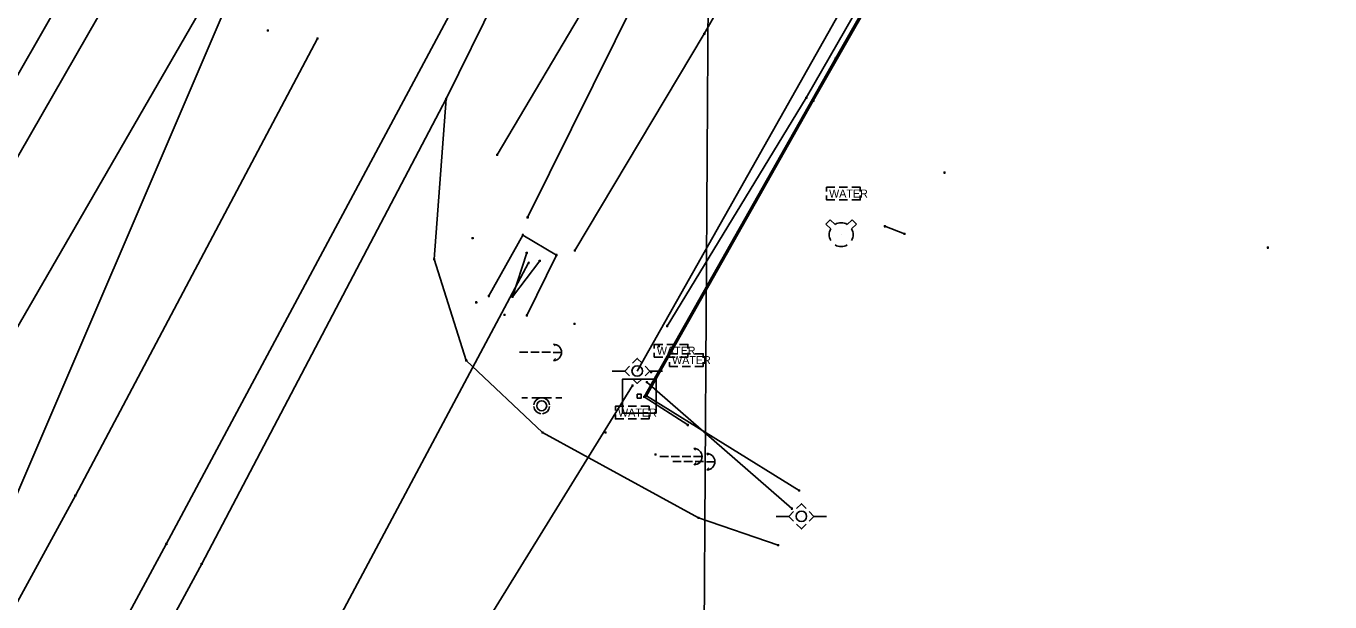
# Model space of a CAD drawing. Extents: x 1954856 to 2011933, y 399149 to 426294.
# Drawn here: x 2006462.2 to 2006616.9, y 401965.3 to 402033.7 of the extents above; entities that cross this region are included whole.
import ezdxf

# ---------------------------------------------------------------- set-up
doc = ezdxf.new("R2010")
doc.units = 0
for name, color, linetype in [('BankMent_ep', 7, 'Continuous'), ('BaselineSurvey', 7, 'Continuous'), ('Driveway_ep', 7, 'Continuous'), ('ElecAer_ep', 7, 'Continuous'), ('EndTreatMES_ep', 7, 'Continuous'), ('Fence_ep', 7, 'Continuous'), ('FireHydrant_ep', 7, 'Continuous'), ('FlowLineInvert_ep', 7, 'Continuous'), ('GovTwpRgeLine_ep', 7, 'Continuous'), ('GuyWireAnchor_ep', 7, 'Continuous'), ('MeterWater_ep', 7, 'Continuous'), ('MonumentCC_ep', 7, 'Continuous'), ('PavtAsphalt_ep', 7, 'Continuous'), ('PipeCulvert_ep', 7, 'Continuous'), ('PMRK_ep', 7, 'Continuous'), ('PointLocator_ep', 7, 'Continuous'), ('PoleShared_ep', 7, 'Continuous'), ('ShldrPaved_ep', 7, 'Continuous'), ('SignSingle_ep', 7, 'Continuous'), ('WaterB_ep', 7, 'Continuous')]:
    doc.layers.add(name, color=color, linetype=linetype)

msp = doc.modelspace()

# ---------------------------------------------------------------- linework, layer by layer
at = {"layer": 'BankMent_ep'}
msp.add_line((2006518.06, 402018.39), (2006530.32, 402039.07), dxfattribs=at)
for points in [[(2006521.67, 402010.95), (2006534.68, 402037.21), (2006577.7, 402108.71), (2006586.6, 402125.35), (2006592.77, 402136.09)], [(2006527.27, 402007.04), (2006542.64, 402032.74), (2006583.85, 402104.85), (2006594.17, 402121.51), (2006599.57, 402131.14)], [(2006538.23, 401998.06), (2006554.74, 402025.13), (2006596.91, 402098.52), (2006605.55, 402113.85), (2006610.04, 402126.13)]]:
    msp.add_lwpolyline(points, dxfattribs=at)
at = {"layer": 'BaselineSurvey'}
msp.add_lwpolyline([(2006095.1, 401364.22), (2006751.44, 402500.64), (2007687.69, 404121.69)], dxfattribs=at)
at = {"layer": 'Driveway_ep'}
msp.add_lwpolyline([(2006512.02, 402025.04), (2006510.58, 402006), (2006514.39, 401993.98), (2006523.44, 401985.42), (2006541.96, 401975.28), (2006551.4, 401972.05)], dxfattribs=at)
at = {"layer": 'ElecAer_ep'}
for points in [[(2006534.68, 401992.72), (2006720.73, 402322.24), (2006754.67, 402382.35)], [(2006462.32, 401874.62), (2006534.11, 401990.99)], [(2006535.81, 401991.41), (2006553.03, 401976.39)]]:
    msp.add_lwpolyline(points, dxfattribs=at)
at = {"layer": 'EndTreatMES_ep'}
for p, q in [((2006517.08, 402001.63), (2006521.12, 402008.86)), ((2006521.12, 402008.86), (2006525.08, 402006.48)), ((2006525.08, 402006.48), (2006521.57, 401999.32))]:
    msp.add_line(p, q, dxfattribs=at)
msp.add_lwpolyline([(2006523.1, 402005.79), (2006519.86, 402001.54), (2006521.56, 402006.75)], dxfattribs=at)
at = {"layer": 'Fence_ep'}
for points in [[(2006540.67, 401986.32), (2006535.51, 401989.65), (2006558.22, 402029.79), (2006609.19, 402119), (2006624.81, 402146.2)], [(2006553.9, 401978.53), (2006535.79, 401989.79), (2006555.57, 402024.8), (2006597.81, 402098.72), (2006606.19, 402113.32)]]:
    msp.add_lwpolyline(points, dxfattribs=at)
at = {"layer": 'FireHydrant_ep'}
for p, q in [((2006557.05, 402010.14), (2006557.58, 402010.68)), ((2006557.58, 402010.68), (2006558.16, 402010.12)), ((2006560.18, 402010.68), (2006559.6, 402010.12)), ((2006560.7, 402010.14), (2006560.18, 402010.68)), ((2006557.05, 402010.14), (2006557.64, 402009.58)), ((2006558.88, 402008.9), (2006558.88, 402008.9)), ((2006560.7, 402010.14), (2006560.12, 402009.58))]:
    msp.add_line(p, q, dxfattribs=at)
for start, end in [(59.4735, 120.5265), (151.2674, 208.7326), (331.2674, 28.7326), (239.4735, 300.5265)]:
    msp.add_arc((2006558.88, 402008.9), 1.42, start, end, dxfattribs=at)
at = {"layer": 'FlowLineInvert_ep'}
for p, q in [((2006521.88, 402005.47), (2006521.7, 402005.64)), ((2006521.88, 402005.64), (2006521.7, 402005.47)), ((2006521.79, 402005.55), (2006521.79, 402005.55))]:
    msp.add_line(p, q, dxfattribs=at)
at = {"layer": 'GovTwpRgeLine_ep'}
msp.add_line((2006528.85, 399746.53), (2006545.38, 402407.42), dxfattribs=at)
at = {"layer": 'GuyWireAnchor_ep'}
for p, q in [((2006520.7, 401994.94), (2006521.7, 401994.94)), ((2006522.04, 401994.94), (2006523.04, 401994.94)), ((2006523.37, 401994.94), (2006524.37, 401994.94)), ((2006524.7, 401994.93), (2006525.7, 401994.93)), ((2006524.73, 401995.9), (2006524.92, 401995.71)), ((2006525.7, 401994.93), (2006525.7, 401994.93)), ((2006524.74, 401993.95), (2006524.98, 401994.19)), ((2006537.37, 401982.57), (2006538.37, 401982.57)), ((2006538.7, 401982.57), (2006539.7, 401982.57)), ((2006540.03, 401982.57), (2006541.03, 401982.57)), ((2006541.37, 401982.56), (2006542.37, 401982.56)), ((2006541.39, 401983.53), (2006541.59, 401983.34)), ((2006542.37, 401982.56), (2006542.37, 401982.56)), ((2006542.92, 401982.93), (2006543.11, 401982.74)), ((2006538.89, 401981.97), (2006539.89, 401981.97)), ((2006540.22, 401981.97), (2006541.22, 401981.97)), ((2006541.41, 401981.58), (2006541.65, 401981.82)), ((2006541.56, 401981.97), (2006542.56, 401981.97)), ((2006542.89, 401981.96), (2006543.89, 401981.96)), ((2006542.93, 401980.98), (2006543.17, 401981.22)), ((2006543.89, 401981.96), (2006543.89, 401981.96))]:
    msp.add_line(p, q, dxfattribs=at)
for centre in [(2006524.73, 401994.93), (2006541.4, 401982.56), (2006542.92, 401981.96)]:
    msp.add_arc(centre, 0.973, 271.14, 90.0059, dxfattribs=at)
at = {"layer": 'MeterWater_ep'}
for p, q in [((2006559.14, 402013.78), (2006559.14, 402013.78)), ((2006538.7, 401995.13), (2006538.7, 401995.13)), ((2006540.51, 401994.02), (2006540.51, 401994.02)), ((2006534.09, 401987.79), (2006534.09, 401987.79))]:
    msp.add_line(p, q, dxfattribs=at)
for points in [[(2006557.14, 402014.03), (2006557.14, 402014.53), (2006558.14, 402014.53)], [(2006558.14, 402013.03), (2006557.14, 402013.03), (2006557.14, 402013.53)], [(2006558.64, 402014.53), (2006559.64, 402014.53)], [(2006560.14, 402014.53), (2006561.14, 402014.53), (2006561.14, 402014.03)], [(2006561.14, 402013.53), (2006561.14, 402013.03), (2006560.14, 402013.03)], [(2006559.64, 402013.03), (2006558.64, 402013.03)], [(2006536.7, 401995.38), (2006536.7, 401995.88), (2006537.7, 401995.88)], [(2006537.7, 401994.38), (2006536.7, 401994.38), (2006536.7, 401994.88)], [(2006538.2, 401995.88), (2006539.2, 401995.88)], [(2006539.7, 401995.88), (2006540.7, 401995.88), (2006540.7, 401995.38)], [(2006540.7, 401994.88), (2006540.7, 401994.38), (2006539.7, 401994.38)], [(2006539.2, 401994.38), (2006538.2, 401994.38)], [(2006538.51, 401994.27), (2006538.51, 401994.77), (2006539.51, 401994.77)], [(2006539.51, 401993.26), (2006538.51, 401993.26), (2006538.51, 401993.77)], [(2006540.01, 401994.77), (2006541.01, 401994.77)], [(2006541.01, 401993.26), (2006540.01, 401993.26)], [(2006541.51, 401994.77), (2006542.51, 401994.77), (2006542.51, 401994.27)], [(2006542.51, 401993.77), (2006542.51, 401993.26), (2006541.51, 401993.26)], [(2006532.09, 401988.04), (2006532.09, 401988.54), (2006533.09, 401988.54)], [(2006533.09, 401987.04), (2006532.09, 401987.04), (2006532.09, 401987.54)], [(2006533.59, 401988.54), (2006534.59, 401988.54)], [(2006535.09, 401988.54), (2006536.09, 401988.54), (2006536.09, 401988.04)], [(2006536.09, 401987.54), (2006536.09, 401987.04), (2006535.09, 401987.04)], [(2006534.59, 401987.04), (2006533.59, 401987.04)]]:
    msp.add_lwpolyline(points, dxfattribs=at)
at = {"layer": 'MonumentCC_ep'}
msp.add_line((2006534.92, 401989.74), (2006534.92, 401989.74), dxfattribs=at)
msp.add_lwpolyline([(2006532.92, 401987.73), (2006536.92, 401987.73), (2006536.92, 401991.74), (2006532.92, 401991.74), (2006532.92, 401987.73)], dxfattribs=at)
msp.add_lwpolyline([(2006534.68, 401989.5), (2006534.68, 401989.97), (2006535.16, 401989.97), (2006535.16, 401989.5)], close=True, dxfattribs=at)
at = {"layer": 'PavtAsphalt_ep'}
for p, q in [((2006486.83, 402062.9), (2006445.85, 401991.54)), ((2006478.79, 401972.18), (2006518.02, 402045.52))]:
    msp.add_line(p, q, dxfattribs=at)
msp.add_lwpolyline([(2006359.89, 401758.81), (2006367.15, 401771.41), (2006374.34, 401784.06), (2006381.49, 401796.73), (2006387.49, 401807.37), (2006393.48, 401818.01), (2006399.46, 401828.66), (2006409.74, 401847.01), (2006420.01, 401865.38), (2006430.26, 401883.75), (2006433.55, 401889.65), (2006436.84, 401895.56), (2006440.13, 401901.47), (2006453.14, 401924.97), (2006466.04, 401948.54), (2006478.79, 401972.18)], dxfattribs=at)
at = {"layer": 'PipeCulvert_ep'}
msp.add_lwpolyline([(2006521.79, 402005.55), (2006493.24, 401952.06)], dxfattribs=at)
at = {"layer": 'PMRK_ep'}
msp.add_line((2006454.18, 401962.09), (2006486.86, 402038.25), dxfattribs=at)
msp.add_lwpolyline([(2006391.58, 401838.69), (2006429.54, 401907.47), (2006468, 401977.95), (2006496.74, 402032.18)], dxfattribs=at)
at = {"layer": 'PointLocator_ep'}
for p, q in [((2006490.97, 402033.13), (2006490.72, 402033.13)), ((2006490.85, 402033.01), (2006490.85, 402033.26)), ((2006490.85, 402033.13), (2006490.85, 402033.13)), ((2006496.87, 402032.18), (2006496.62, 402032.18)), ((2006496.74, 402032.06), (2006496.74, 402032.31)), ((2006496.74, 402032.18), (2006496.74, 402032.18)), ((2006542.77, 402032.74), (2006542.52, 402032.74)), ((2006542.64, 402032.62), (2006542.64, 402032.87)), ((2006542.64, 402032.74), (2006542.64, 402032.74)), ((2006558.34, 402029.79), (2006558.09, 402029.79)), ((2006558.22, 402029.67), (2006558.22, 402029.92)), ((2006558.22, 402029.79), (2006558.22, 402029.79)), ((2006512.14, 402025.04), (2006511.89, 402025.04)), ((2006512.02, 402024.91), (2006512.02, 402025.16)), ((2006512.02, 402025.04), (2006512.02, 402025.04)), ((2006554.87, 402025.13), (2006554.62, 402025.13)), ((2006554.74, 402025.01), (2006554.74, 402025.26)), ((2006554.74, 402025.13), (2006554.74, 402025.13)), ((2006555.7, 402024.8), (2006555.45, 402024.8)), ((2006555.57, 402024.68), (2006555.57, 402024.93)), ((2006555.57, 402024.8), (2006555.57, 402024.8)), ((2006518.18, 402018.39), (2006517.93, 402018.39)), ((2006518.06, 402018.26), (2006518.06, 402018.51)), ((2006518.06, 402018.39), (2006518.06, 402018.39)), ((2006571.27, 402016.27), (2006571.02, 402016.27)), ((2006571.15, 402016.14), (2006571.15, 402016.39)), ((2006571.15, 402016.27), (2006571.15, 402016.27)), ((2006521.8, 402010.95), (2006521.55, 402010.95)), ((2006521.67, 402010.83), (2006521.67, 402011.08)), ((2006521.67, 402010.95), (2006521.67, 402010.95)), ((2006521.24, 402008.86), (2006520.99, 402008.86)), ((2006521.12, 402008.74), (2006521.12, 402008.99)), ((2006521.12, 402008.86), (2006521.12, 402008.86)), ((2006564.18, 402009.9), (2006563.93, 402009.9)), ((2006564.06, 402009.77), (2006564.06, 402010.02)), ((2006564.06, 402009.9), (2006564.06, 402009.9)), ((2006566.53, 402009), (2006566.28, 402009)), ((2006566.4, 402008.87), (2006566.4, 402009.12)), ((2006566.4, 402009), (2006566.4, 402009)), ((2006515.27, 402008.47), (2006515.02, 402008.47)), ((2006515.14, 402008.35), (2006515.14, 402008.6)), ((2006515.14, 402008.47), (2006515.14, 402008.47)), ((2006609.64, 402007.37), (2006609.39, 402007.37)), ((2006609.52, 402007.24), (2006609.52, 402007.49)), ((2006609.52, 402007.37), (2006609.52, 402007.37)), ((2006510.7, 402006), (2006510.45, 402006)), ((2006510.58, 402005.88), (2006510.58, 402006.13)), ((2006510.58, 402006), (2006510.58, 402006)), ((2006521.68, 402006.75), (2006521.43, 402006.75)), ((2006521.56, 402006.62), (2006521.56, 402006.87)), ((2006521.56, 402006.75), (2006521.56, 402006.75)), ((2006523.23, 402005.79), (2006522.98, 402005.79)), ((2006523.1, 402005.67), (2006523.1, 402005.92)), ((2006523.1, 402005.79), (2006523.1, 402005.79)), ((2006525.2, 402006.48), (2006524.95, 402006.48)), ((2006525.08, 402006.36), (2006525.08, 402006.61)), ((2006525.08, 402006.48), (2006525.08, 402006.48)), ((2006527.39, 402007.04), (2006527.14, 402007.04)), ((2006527.27, 402006.91), (2006527.27, 402007.16)), ((2006527.27, 402007.04), (2006527.27, 402007.04)), ((2006515.58, 402000.74), (2006515.58, 402000.99)), ((2006517.2, 402001.63), (2006516.95, 402001.63)), ((2006517.08, 402001.5), (2006517.08, 402001.75)), ((2006517.08, 402001.63), (2006517.08, 402001.63)), ((2006519.99, 402001.54), (2006519.74, 402001.54)), ((2006519.86, 402001.42), (2006519.86, 402001.67)), ((2006519.86, 402001.54), (2006519.86, 402001.54)), ((2006515.71, 402000.87), (2006515.46, 402000.87)), ((2006515.58, 402000.87), (2006515.58, 402000.87)), ((2006518.91, 401999.25), (2006518.91, 401999.5)), ((2006521.57, 401999.2), (2006521.57, 401999.45)), ((2006519.04, 401999.38), (2006518.79, 401999.38)), ((2006518.91, 401999.38), (2006518.91, 401999.38)), ((2006521.69, 401999.32), (2006521.44, 401999.32)), ((2006521.57, 401999.32), (2006521.57, 401999.32)), ((2006527.36, 401998.33), (2006527.11, 401998.33)), ((2006527.24, 401998.2), (2006527.24, 401998.45)), ((2006527.24, 401998.33), (2006527.24, 401998.33)), ((2006538.36, 401998.06), (2006538.11, 401998.06)), ((2006538.23, 401997.94), (2006538.23, 401998.19)), ((2006538.23, 401998.06), (2006538.23, 401998.06)), ((2006537.38, 401995.68), (2006537.13, 401995.68)), ((2006537.26, 401995.56), (2006537.26, 401995.81)), ((2006537.26, 401995.68), (2006537.26, 401995.68)), ((2006514.52, 401993.98), (2006514.27, 401993.98)), ((2006514.39, 401993.86), (2006514.39, 401994.11)), ((2006514.39, 401993.98), (2006514.39, 401993.98)), ((2006536.47, 401992.59), (2006536.22, 401992.59)), ((2006536.34, 401992.46), (2006536.34, 401992.71)), ((2006536.34, 401992.59), (2006536.34, 401992.59)), ((2006534.24, 401990.99), (2006533.99, 401990.99)), ((2006534.11, 401990.86), (2006534.11, 401991.11)), ((2006534.11, 401990.99), (2006534.11, 401990.99)), ((2006535.93, 401991.41), (2006535.68, 401991.41)), ((2006535.81, 401991.28), (2006535.81, 401991.53)), ((2006535.81, 401991.41), (2006535.81, 401991.41)), ((2006535.63, 401989.65), (2006535.38, 401989.65)), ((2006535.51, 401989.52), (2006535.51, 401989.77)), ((2006535.51, 401989.65), (2006535.51, 401989.65)), ((2006535.92, 401989.79), (2006535.67, 401989.79)), ((2006535.79, 401989.67), (2006535.79, 401989.92)), ((2006535.79, 401989.79), (2006535.79, 401989.79)), ((2006523.44, 401985.3), (2006523.44, 401985.55)), ((2006530.92, 401985.31), (2006530.92, 401985.56)), ((2006540.79, 401986.32), (2006540.54, 401986.32)), ((2006540.67, 401986.19), (2006540.67, 401986.44)), ((2006540.67, 401986.32), (2006540.67, 401986.32)), ((2006523.57, 401985.42), (2006523.32, 401985.42)), ((2006523.44, 401985.42), (2006523.44, 401985.42)), ((2006531.05, 401985.43), (2006530.8, 401985.43)), ((2006530.92, 401985.43), (2006530.92, 401985.43)), ((2006536.96, 401982.81), (2006536.71, 401982.81)), ((2006536.83, 401982.68), (2006536.83, 401982.93)), ((2006536.83, 401982.81), (2006536.83, 401982.81)), ((2006468.12, 401977.95), (2006467.87, 401977.95)), ((2006468, 401977.82), (2006468, 401978.07)), ((2006468, 401977.95), (2006468, 401977.95)), ((2006554.03, 401978.53), (2006553.78, 401978.53)), ((2006553.9, 401978.41), (2006553.9, 401978.66)), ((2006553.9, 401978.53), (2006553.9, 401978.53)), ((2006553.15, 401976.39), (2006552.9, 401976.39)), ((2006553.03, 401976.26), (2006553.03, 401976.51)), ((2006553.03, 401976.39), (2006553.03, 401976.39)), ((2006542.08, 401975.28), (2006541.83, 401975.28)), ((2006541.96, 401975.16), (2006541.96, 401975.41)), ((2006541.96, 401975.28), (2006541.96, 401975.28)), ((2006478.92, 401972.18), (2006478.67, 401972.18)), ((2006478.79, 401972.06), (2006478.79, 401972.31)), ((2006478.79, 401972.18), (2006478.79, 401972.18)), ((2006551.53, 401972.05), (2006551.28, 401972.05)), ((2006551.4, 401971.92), (2006551.4, 401972.17)), ((2006551.4, 401972.05), (2006551.4, 401972.05)), ((2006483.11, 401969.83), (2006482.86, 401969.83)), ((2006482.99, 401969.7), (2006482.99, 401969.95)), ((2006482.99, 401969.83), (2006482.99, 401969.83))]:
    msp.add_line(p, q, dxfattribs=at)
at = {"layer": 'PoleShared_ep'}
for p, q in [((2006533.2, 401992.72), (2006533.76, 401993.29)), ((2006531.7, 401992.72), (2006533.2, 401992.72)), ((2006533.76, 401992.16), (2006533.2, 401992.72)), ((2006534.68, 401992.72), (2006534.68, 401992.72)), ((2006537.67, 401992.72), (2006536.17, 401992.72)), ((2006551.17, 401975.47), (2006552.67, 401975.47)), ((2006552.67, 401975.47), (2006553.23, 401976.04)), ((2006553.23, 401974.91), (2006552.67, 401975.47)), ((2006554.16, 401975.47), (2006554.16, 401975.47)), ((2006557.14, 401975.47), (2006555.64, 401975.47))]:
    msp.add_line(p, q, dxfattribs=at)
for points in [[(2006534.12, 401993.65), (2006534.68, 401994.21), (2006535.25, 401993.64)], [(2006535.61, 401993.29), (2006536.17, 401992.72), (2006535.61, 401992.16)], [(2006535.25, 401991.8), (2006534.68, 401991.24), (2006534.12, 401991.8)], [(2006553.59, 401976.4), (2006554.16, 401976.96), (2006554.72, 401976.39)], [(2006555.08, 401976.04), (2006555.64, 401975.47), (2006555.08, 401974.91)], [(2006554.72, 401974.55), (2006554.16, 401973.99), (2006553.59, 401974.55)]]:
    msp.add_lwpolyline(points, dxfattribs=at)
for centre, start, end in [((2006534.68, 401992.72), 90, 270), ((2006534.68, 401992.72), 270, 90), ((2006554.16, 401975.47), 90, 270), ((2006554.16, 401975.47), 270, 90)]:
    msp.add_arc(centre, 0.625, start, end, dxfattribs=at)
at = {"layer": 'ShldrPaved_ep'}
for p, q in [((2006482.52, 402065.14), (2006441.61, 401993.8)), ((2006512.02, 402025.04), (2006521.25, 402043.84)), ((2006482.99, 401969.83), (2006512.02, 402025.04)), ((2006472.31, 401950.15), (2006482.99, 401969.83))]:
    msp.add_line(p, q, dxfattribs=at)
at = {"layer": 'SignSingle_ep'}
for p, q in [((2006520.97, 401989.55), (2006521.67, 401989.55)), ((2006522.17, 401989.55), (2006524.52, 401989.55)), ((2006523.34, 401988.6), (2006523.34, 401988.6)), ((2006525.02, 401989.55), (2006525.72, 401989.55))]:
    msp.add_line(p, q, dxfattribs=at)
msp.add_circle((2006523.34, 401988.6), 0.594, dxfattribs=at)
for start, end in [(96.0423, 173.9577), (6.0423, 83.9577), (186.0423, 263.9577), (276.0423, 353.9577)]:
    msp.add_arc((2006523.34, 401988.6), 0.95, start, end, dxfattribs=at)
at = {"layer": 'WaterB_ep'}
msp.add_lwpolyline([(2006564.06, 402009.9), (2006566.4, 402009)], dxfattribs=at)

# ---------------------------------------------------------------- texts
at = {"layer": 'MeterWater_ep'}
for p in [(2006557.45, 402013.31), (2006537.01, 401994.66), (2006538.82, 401993.54), (2006532.4, 401987.32)]:
    msp.add_text('WATER', height=0.95, dxfattribs=at).set_placement(p)

doc.saveas('drawing.dxf')
